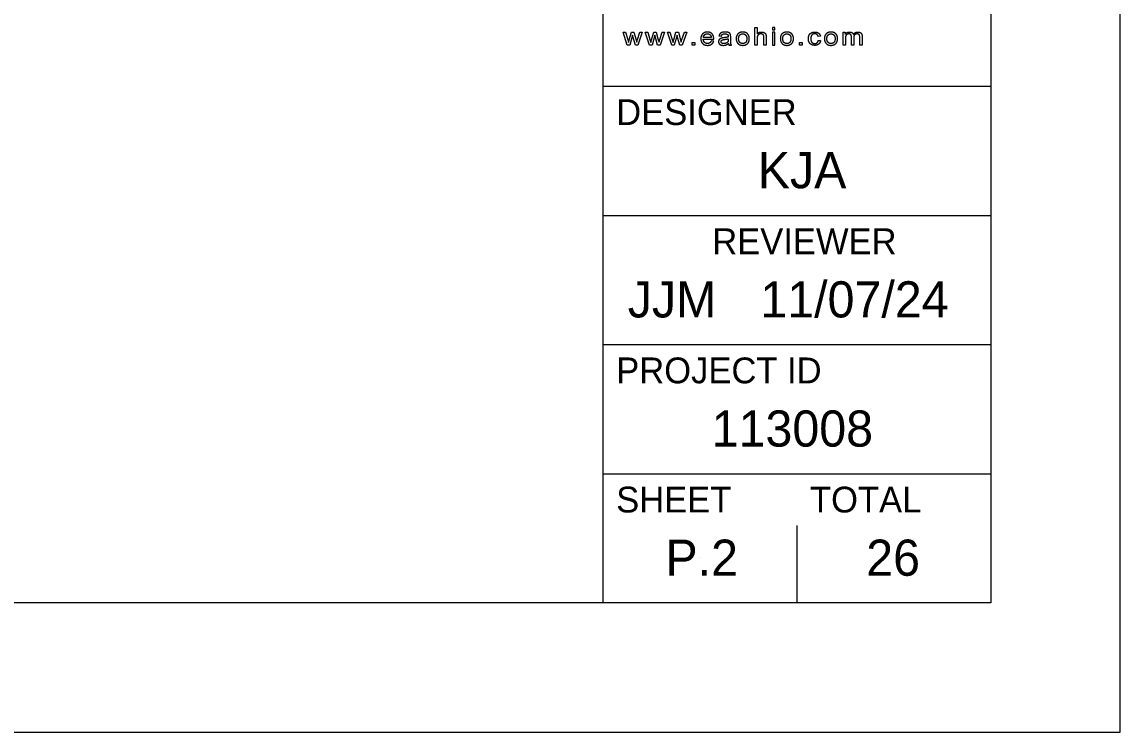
# Model space of a CAD drawing. Extents: x -91 to 170, y -6 to 110.
# Drawn here: x 148.75 to 170, y 0 to 13.74 of the extents above; entities that cross this region are included whole.
import ezdxf

# ---------------------------------------------------------------- set-up
doc = ezdxf.new("R2010")
doc.units = 0
for name, color, linetype in [('SH_Border', 7, 'Continuous'), ('SH_Cut_Line', 7, 'Continuous'), ('SH_Data', 7, 'Continuous'), ('TX_X_20', 7, 'Continuous')]:
    doc.layers.add(name, color=color, linetype=linetype)

msp = doc.modelspace()

# ---------------------------------------------------------------- linework, layer by layer
at = {"layer": 'SH_Border'}
for p, q in [((160, 2.5), (160, 107.5)), ((160, 12.5), (167.5, 12.5)), ((160, 10), (167.5, 10)), ((160, 7.5), (167.5, 7.5)), ((160, 5), (167.5, 5))]:
    msp.add_line(p, q, dxfattribs=at)
msp.add_lwpolyline([(7.5, 107.5), (167.5, 107.5), (167.5, 2.5), (7.5, 2.5)], close=True, dxfattribs=at)
at = {"layer": 'SH_Cut_Line'}
msp.add_lwpolyline([(0, 0), (170, 0), (170, 110), (0, 110)], close=True, dxfattribs=at)
at = {"layer": 'SH_Data'}
for p, q in [((163.75, 2.5), (163.75, 4)), ((161.875, 3.375), (161.875, 3.375))]:
    msp.add_line(p, q, dxfattribs=at)
at = {"layer": 'TX_X_20'}
for p, q in [((161.935, 13.41), (162.137, 13.41)), ((162.089, 13.445), (161.938, 13.445)), ((162.238, 13.474), (162.283, 13.468)), ((162.419, 13.421), (162.419, 13.406)), ((162.465, 13.401), (162.465, 13.457)), ((162.572, 13.421), (162.572, 13.421)), ((162.619, 13.421), (162.619, 13.421)), ((163.426, 13.421), (163.426, 13.421)), ((163.473, 13.421), (163.473, 13.421)), ((164.201, 13.472), (164.156, 13.466)), ((164.16, 13.388), (164.205, 13.383)), ((164.28, 13.421), (164.28, 13.421)), ((164.327, 13.421), (164.327, 13.421)), ((162.136, 13.372), (162.088, 13.377)), ((162.423, 13.328), (162.423, 13.328)), ((162.432, 13.298), (162.48, 13.298))]:
    msp.add_line(p, q, dxfattribs=at)
for points in [[(162.978, 13.433), (162.978, 13.298), (162.932, 13.298), (162.932, 13.638), (162.978, 13.638), (162.978, 13.516)], [(160.503, 13.4), (160.547, 13.544), (160.594, 13.544), (160.634, 13.401), (160.648, 13.354), (160.663, 13.402), (160.71, 13.544), (160.755, 13.544), (160.67, 13.298), (160.622, 13.298), (160.579, 13.445), (160.568, 13.487), (160.513, 13.298), (160.465, 13.298), (160.383, 13.544), (160.43, 13.544), (160.474, 13.402), (160.489, 13.349)], [(160.933, 13.4), (160.976, 13.544), (161.024, 13.544), (161.064, 13.401), (161.078, 13.354), (161.093, 13.402), (161.14, 13.544), (161.185, 13.544), (161.099, 13.298), (161.052, 13.298), (161.009, 13.445), (160.998, 13.487), (160.943, 13.298), (160.895, 13.298), (160.813, 13.544), (160.86, 13.544), (160.903, 13.402), (160.919, 13.349)], [(161.363, 13.4), (161.406, 13.544), (161.454, 13.544), (161.494, 13.401), (161.507, 13.354), (161.523, 13.402), (161.57, 13.544), (161.614, 13.544), (161.529, 13.298), (161.482, 13.298), (161.439, 13.445), (161.428, 13.487), (161.373, 13.298), (161.325, 13.298), (161.243, 13.544), (161.29, 13.544), (161.333, 13.402), (161.349, 13.349)], [(163.152, 13.454), (163.152, 13.298), (163.107, 13.298), (163.107, 13.454)], [(164.686, 13.426), (164.686, 13.298), (164.64, 13.298), (164.64, 13.544), (164.681, 13.544), (164.681, 13.51)], [(164.847, 13.441), (164.847, 13.298), (164.801, 13.298), (164.801, 13.458)], [(165.008, 13.467), (165.008, 13.298), (164.962, 13.298), (164.962, 13.453)]]:
    msp.add_lwpolyline(points, dxfattribs=at)
for points in [[(163.275, 13.59), (163.321, 13.59), (163.321, 13.638), (163.275, 13.638)], [(163.275, 13.298), (163.321, 13.298), (163.321, 13.544), (163.275, 13.544)], [(161.718, 13.298), (161.718, 13.345), (161.771, 13.345), (161.771, 13.298)], [(163.799, 13.298), (163.799, 13.345), (163.851, 13.345), (163.851, 13.298)]]:
    msp.add_lwpolyline(points, close=True, dxfattribs=at)
for points in [[(160.489, 13.349), (160.49, 13.353), (160.503, 13.4)], [(160.919, 13.349), (160.92, 13.353), (160.933, 13.4)], [(161.349, 13.349), (161.35, 13.353), (161.363, 13.4)], [(161.923, 13.515), (161.888, 13.481), (161.888, 13.419)], [(161.888, 13.419), (161.888, 13.359), (161.923, 13.326)], [(162.014, 13.55), (161.958, 13.55), (161.923, 13.515)], [(161.96, 13.348), (161.938, 13.37), (161.935, 13.41)], [(161.938, 13.445), (161.94, 13.477), (161.961, 13.496)], [(161.961, 13.496), (161.983, 13.516), (162.015, 13.516)], [(162.103, 13.516), (162.069, 13.55), (162.014, 13.55)], [(162.015, 13.516), (162.05, 13.516), (162.072, 13.491)], [(162.072, 13.491), (162.086, 13.476), (162.089, 13.445)], [(162.137, 13.421), (162.137, 13.482), (162.103, 13.516)], [(162.137, 13.41), (162.137, 13.418), (162.137, 13.421)], [(162.239, 13.396), (162.23, 13.381), (162.23, 13.363)], [(162.258, 13.516), (162.244, 13.5), (162.238, 13.474)], [(162.263, 13.42), (162.248, 13.411), (162.239, 13.396)], [(162.299, 13.541), (162.272, 13.532), (162.258, 13.516)], [(162.296, 13.433), (162.278, 13.429), (162.263, 13.42)], [(162.283, 13.468), (162.291, 13.495), (162.306, 13.505)], [(162.286, 13.384), (162.292, 13.393), (162.304, 13.397)], [(162.337, 13.44), (162.31, 13.437), (162.296, 13.433)], [(162.36, 13.55), (162.325, 13.55), (162.299, 13.541)], [(162.304, 13.397), (162.316, 13.402), (162.344, 13.406)], [(162.306, 13.505), (162.322, 13.515), (162.354, 13.515)], [(162.419, 13.454), (162.393, 13.446), (162.337, 13.44)], [(162.344, 13.406), (162.394, 13.412), (162.419, 13.421)], [(162.354, 13.515), (162.388, 13.515), (162.406, 13.501)], [(162.417, 13.542), (162.395, 13.55), (162.36, 13.55)], [(162.406, 13.501), (162.419, 13.491), (162.419, 13.465)], [(162.419, 13.406), (162.419, 13.379), (162.411, 13.364)], [(162.449, 13.524), (162.438, 13.535), (162.417, 13.542)], [(162.419, 13.465), (162.419, 13.463), (162.419, 13.454)], [(162.463, 13.495), (162.459, 13.512), (162.449, 13.524)], [(162.465, 13.457), (162.465, 13.485), (162.463, 13.495)], [(162.468, 13.327), (162.465, 13.343), (162.465, 13.401)], [(162.614, 13.522), (162.572, 13.489), (162.572, 13.421)], [(162.572, 13.421), (162.572, 13.359), (162.607, 13.326)], [(162.699, 13.55), (162.649, 13.55), (162.614, 13.522)], [(162.619, 13.421), (162.619, 13.468), (162.642, 13.492)], [(162.642, 13.35), (162.619, 13.374), (162.619, 13.421)], [(162.642, 13.492), (162.664, 13.515), (162.699, 13.515)], [(162.79, 13.517), (162.755, 13.55), (162.699, 13.55)], [(162.699, 13.515), (162.733, 13.515), (162.755, 13.492)], [(162.755, 13.492), (162.778, 13.468), (162.778, 13.422)], [(162.778, 13.422), (162.778, 13.374), (162.756, 13.35)], [(162.826, 13.425), (162.826, 13.483), (162.79, 13.517)], [(162.81, 13.35), (162.826, 13.377), (162.826, 13.425)], [(162.978, 13.516), (163.01, 13.55), (163.059, 13.55)], [(162.985, 13.478), (162.978, 13.462), (162.978, 13.433)], [(163.011, 13.504), (162.993, 13.495), (162.985, 13.478)], [(163.049, 13.514), (163.029, 13.514), (163.011, 13.504)], [(163.092, 13.499), (163.077, 13.514), (163.049, 13.514)], [(163.059, 13.55), (163.089, 13.55), (163.111, 13.539)], [(163.107, 13.454), (163.107, 13.485), (163.092, 13.499)], [(163.111, 13.539), (163.133, 13.528), (163.143, 13.509)], [(163.143, 13.509), (163.152, 13.49), (163.152, 13.454)], [(163.468, 13.522), (163.426, 13.489), (163.426, 13.421)], [(163.426, 13.421), (163.426, 13.359), (163.461, 13.326)], [(163.553, 13.55), (163.503, 13.55), (163.468, 13.522)], [(163.473, 13.421), (163.473, 13.468), (163.496, 13.492)], [(163.496, 13.35), (163.473, 13.374), (163.473, 13.421)], [(163.496, 13.492), (163.519, 13.515), (163.553, 13.515)], [(163.644, 13.517), (163.609, 13.55), (163.553, 13.55)], [(163.553, 13.515), (163.587, 13.515), (163.61, 13.492)], [(163.61, 13.492), (163.632, 13.468), (163.632, 13.422)], [(163.632, 13.422), (163.632, 13.374), (163.61, 13.35)], [(163.68, 13.425), (163.68, 13.483), (163.644, 13.517)], [(163.664, 13.35), (163.68, 13.377), (163.68, 13.425)], [(163.969, 13.42), (163.969, 13.46), (163.984, 13.49)], [(164.003, 13.325), (163.969, 13.358), (163.969, 13.42)], [(163.984, 13.49), (163.998, 13.52), (164.028, 13.535)], [(164.038, 13.493), (164.017, 13.47), (164.017, 13.421)], [(164.017, 13.421), (164.017, 13.372), (164.038, 13.349)], [(164.028, 13.535), (164.058, 13.55), (164.093, 13.55)], [(164.095, 13.516), (164.06, 13.516), (164.038, 13.493)], [(164.093, 13.55), (164.137, 13.55), (164.165, 13.529)], [(164.134, 13.503), (164.118, 13.516), (164.095, 13.516)], [(164.156, 13.466), (164.15, 13.49), (164.134, 13.503)], [(164.137, 13.342), (164.156, 13.357), (164.16, 13.388)], [(164.165, 13.529), (164.193, 13.509), (164.201, 13.472)], [(164.322, 13.522), (164.28, 13.489), (164.28, 13.421)], [(164.28, 13.421), (164.28, 13.359), (164.315, 13.326)], [(164.407, 13.55), (164.357, 13.55), (164.322, 13.522)], [(164.327, 13.421), (164.327, 13.468), (164.35, 13.492)], [(164.35, 13.35), (164.327, 13.374), (164.327, 13.421)], [(164.35, 13.492), (164.373, 13.515), (164.407, 13.515)], [(164.498, 13.517), (164.463, 13.55), (164.407, 13.55)], [(164.407, 13.515), (164.441, 13.515), (164.464, 13.492)], [(164.464, 13.492), (164.486, 13.468), (164.486, 13.422)], [(164.486, 13.422), (164.486, 13.374), (164.464, 13.35)], [(164.534, 13.425), (164.534, 13.483), (164.498, 13.517)], [(164.518, 13.35), (164.534, 13.377), (164.534, 13.425)], [(164.681, 13.51), (164.694, 13.528), (164.715, 13.539)], [(164.693, 13.477), (164.686, 13.459), (164.686, 13.426)], [(164.717, 13.504), (164.701, 13.495), (164.693, 13.477)], [(164.715, 13.539), (164.736, 13.55), (164.763, 13.55)], [(164.753, 13.513), (164.734, 13.513), (164.717, 13.504)], [(164.79, 13.5), (164.779, 13.513), (164.753, 13.513)], [(164.763, 13.55), (164.793, 13.55), (164.813, 13.538)], [(164.801, 13.458), (164.801, 13.486), (164.79, 13.5)], [(164.813, 13.538), (164.832, 13.527), (164.84, 13.507)], [(164.84, 13.507), (164.872, 13.55), (164.924, 13.55)], [(164.866, 13.496), (164.847, 13.479), (164.847, 13.441)], [(164.913, 13.513), (164.885, 13.513), (164.866, 13.496)], [(164.941, 13.507), (164.929, 13.513), (164.913, 13.513)], [(164.924, 13.55), (164.964, 13.55), (164.986, 13.529)], [(164.957, 13.489), (164.953, 13.5), (164.941, 13.507)], [(164.962, 13.453), (164.962, 13.478), (164.957, 13.489)], [(164.986, 13.529), (165.008, 13.509), (165.008, 13.467)], [(161.923, 13.326), (161.957, 13.292), (162.017, 13.292)], [(162.017, 13.327), (161.983, 13.327), (161.96, 13.348)], [(162.06, 13.339), (162.042, 13.327), (162.017, 13.327)], [(162.017, 13.292), (162.064, 13.292), (162.094, 13.313)], [(162.088, 13.377), (162.078, 13.351), (162.06, 13.339)], [(162.094, 13.313), (162.125, 13.334), (162.136, 13.372)], [(162.23, 13.363), (162.23, 13.332), (162.254, 13.312)], [(162.254, 13.312), (162.278, 13.292), (162.323, 13.292)], [(162.279, 13.364), (162.279, 13.375), (162.286, 13.384)], [(162.293, 13.336), (162.279, 13.347), (162.279, 13.364)], [(162.334, 13.325), (162.307, 13.325), (162.293, 13.336)], [(162.323, 13.292), (162.35, 13.292), (162.374, 13.3)], [(162.381, 13.336), (162.36, 13.325), (162.334, 13.325)], [(162.374, 13.3), (162.397, 13.309), (162.423, 13.328)], [(162.411, 13.364), (162.402, 13.346), (162.381, 13.336)], [(162.423, 13.328), (162.425, 13.311), (162.432, 13.298)], [(162.48, 13.298), (162.471, 13.312), (162.468, 13.327)], [(162.607, 13.326), (162.642, 13.292), (162.699, 13.292)], [(162.699, 13.327), (162.664, 13.327), (162.642, 13.35)], [(162.756, 13.35), (162.733, 13.327), (162.699, 13.327)], [(162.699, 13.292), (162.734, 13.292), (162.764, 13.307)], [(162.764, 13.307), (162.794, 13.323), (162.81, 13.35)], [(163.461, 13.326), (163.496, 13.292), (163.553, 13.292)], [(163.553, 13.327), (163.519, 13.327), (163.496, 13.35)], [(163.61, 13.35), (163.587, 13.327), (163.553, 13.327)], [(163.553, 13.292), (163.588, 13.292), (163.618, 13.307)], [(163.618, 13.307), (163.648, 13.323), (163.664, 13.35)], [(164.093, 13.292), (164.037, 13.292), (164.003, 13.325)], [(164.038, 13.349), (164.059, 13.327), (164.092, 13.327)], [(164.092, 13.327), (164.119, 13.327), (164.137, 13.342)], [(164.168, 13.316), (164.137, 13.292), (164.093, 13.292)], [(164.205, 13.383), (164.198, 13.34), (164.168, 13.316)], [(164.315, 13.326), (164.35, 13.292), (164.407, 13.292)], [(164.407, 13.327), (164.373, 13.327), (164.35, 13.35)], [(164.464, 13.35), (164.441, 13.327), (164.407, 13.327)], [(164.407, 13.292), (164.443, 13.292), (164.472, 13.307)], [(164.472, 13.307), (164.502, 13.323), (164.518, 13.35)]]:
    msp.add_open_spline(points, degree=2, dxfattribs=at)

# ---------------------------------------------------------------- texts
at = {"layer": 'SH_Data'}
for s, height, p in [('DESIGNER', 0.5, (160.25, 11.75)), ('KJA', 0.7, (162.988, 10.525)), ('REVIEWER', 0.5, (162.109, 9.25)), ('JJM', 0.7, (160.473, 8.025)), ('11/07/24', 0.7, (163.039, 8.025)), ('PROJECT ID', 0.5, (160.25, 6.75)), ('113008', 0.7, (162.097, 5.525)), ('SHEET', 0.5, (160.25, 4.25)), ('TOTAL', 0.5, (164, 4.25)), ('P.2', 0.7, (161.202, 3.025)), ('26', 0.7, (165.088, 3.025))]:
    msp.add_text(s, height=height, dxfattribs=at).set_placement(p)

doc.saveas('drawing.dxf')
